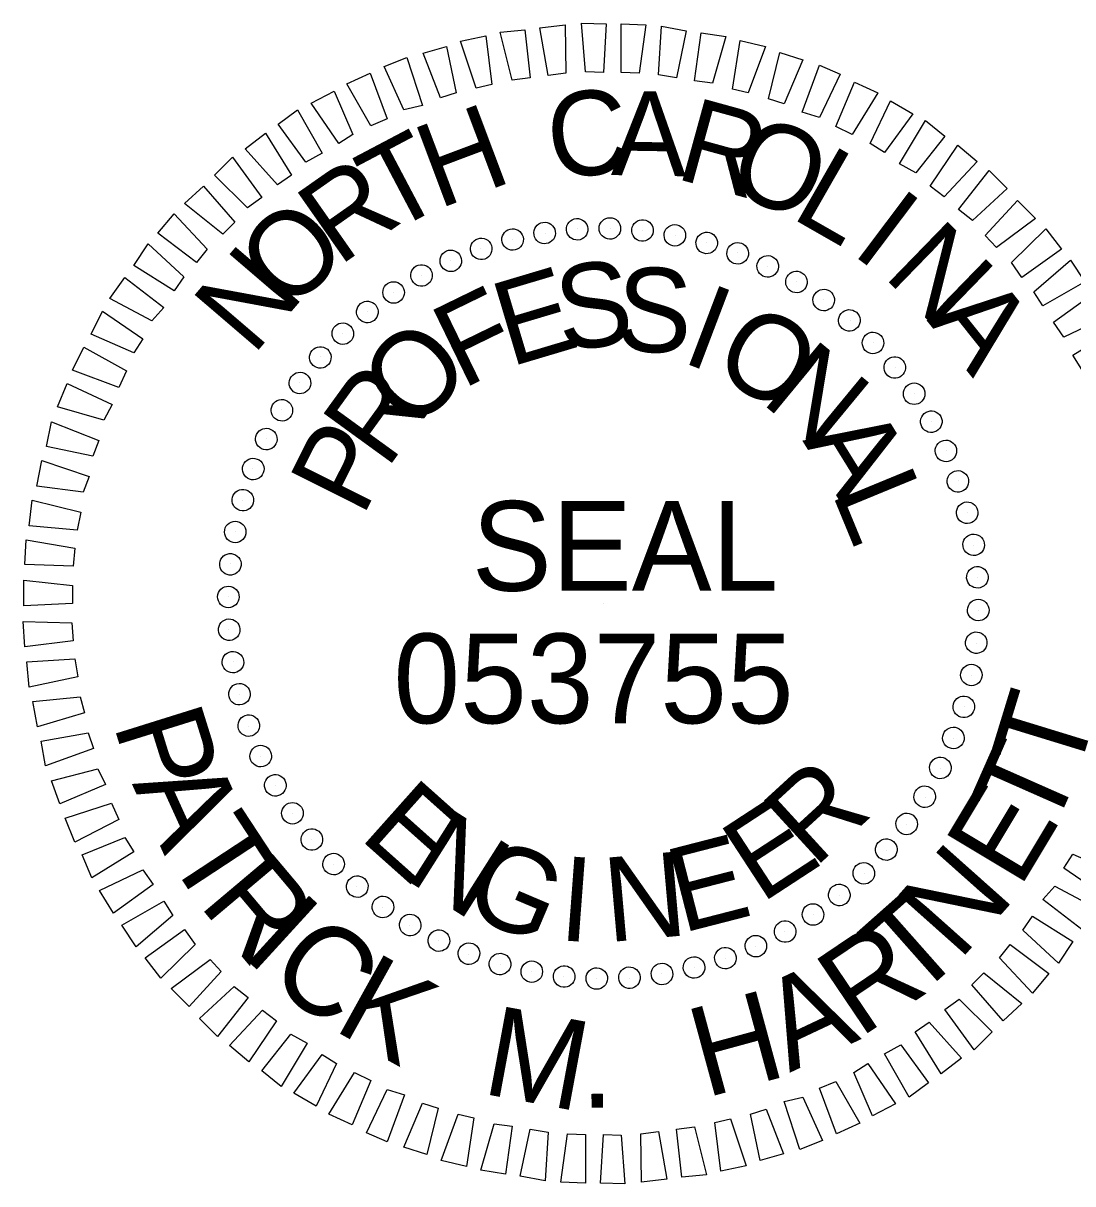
# Model space of a CAD drawing. Extents: x 1184048.9 to 1184122, y 1246638.9 to 1246660.6.
# Drawn here: x 1184117.624 to 1184120.43, y 1246652.546 to 1246655.648 of the extents above; entities that cross this region are included whole.
import ezdxf

# ---------------------------------------------------------------- set-up
doc = ezdxf.new("R2010")
doc.units = 0
doc.layers.add('Sheet PE Seal CELL', color=7, linetype='Continuous')

msp = doc.modelspace()

# ---------------------------------------------------------------- linework, layer by layer
at = {"layer": 'Sheet PE Seal CELL'}
for p, q in [((1184119.1053, 1246655.098), (1184119.1053, 1246655.098)), ((1184119.1932, 1246655.1), (1184119.1932, 1246655.1)), ((1184118.9314, 1246655.07), (1184118.9314, 1246655.07)), ((1184119.0194, 1246655.086), (1184119.0194, 1246655.086)), ((1184119.2812, 1246655.094), (1184119.2812, 1246655.094)), ((1184119.3671, 1246655.08), (1184119.3671, 1246655.08)), ((1184118.8475, 1246655.046), (1184118.8475, 1246655.046)), ((1184119.451, 1246655.062), (1184119.451, 1246655.062)), ((1184118.7676, 1246655.014), (1184118.7676, 1246655.014)), ((1184119.535, 1246655.034), (1184119.535, 1246655.034)), ((1184118.6896, 1246654.9741), (1184118.6896, 1246654.9741)), ((1184119.6149, 1246654.998), (1184119.6149, 1246654.998)), ((1184119.6928, 1246654.9581), (1184119.6928, 1246654.9581)), ((1184118.6137, 1246654.9281), (1184118.6137, 1246654.9281)), ((1184119.7648, 1246654.9081), (1184119.7648, 1246654.9081)), ((1184118.5438, 1246654.8781), (1184118.5438, 1246654.8781)), ((1184119.8347, 1246654.8542), (1184119.8347, 1246654.8542)), ((1184118.4778, 1246654.8182), (1184118.4778, 1246654.8182)), ((1184119.8967, 1246654.7942), (1184119.8967, 1246654.7942)), ((1184118.4179, 1246654.7562), (1184118.4179, 1246654.7562)), ((1184119.9566, 1246654.7283), (1184119.9566, 1246654.7283)), ((1184118.3639, 1246654.6863), (1184118.3639, 1246654.6863)), ((1184120.0066, 1246654.6583), (1184120.0066, 1246654.6583)), ((1184118.3139, 1246654.6143), (1184118.3139, 1246654.6143)), ((1184120.0526, 1246654.5824), (1184120.0526, 1246654.5824)), ((1184118.274, 1246654.5364), (1184118.274, 1246654.5364)), ((1184120.0925, 1246654.5044), (1184120.0925, 1246654.5044)), ((1184118.238, 1246654.4565), (1184118.238, 1246654.4565)), ((1184120.1245, 1246654.4245), (1184120.1245, 1246654.4245)), ((1184118.21, 1246654.3725), (1184118.21, 1246654.3725)), ((1184120.1485, 1246654.3406), (1184120.1485, 1246654.3406)), ((1184118.192, 1246654.2886), (1184118.192, 1246654.2886)), ((1184120.1645, 1246654.2526), (1184120.1645, 1246654.2526)), ((1184118.1781, 1246654.2027), (1184118.1781, 1246654.2027)), ((1184120.1765, 1246654.1667), (1184120.1765, 1246654.1667)), ((1184118.1721, 1246654.1147), (1184118.1721, 1246654.1147)), ((1184119.1753, 1246654.0968), (1184119.1753, 1246654.0968)), ((1184120.1785, 1246654.0788), (1184120.1785, 1246654.0788)), ((1184118.1741, 1246654.0268), (1184118.1741, 1246654.0268)), ((1184120.1725, 1246653.9908), (1184120.1725, 1246653.9908)), ((1184118.186, 1246653.9409), (1184118.186, 1246653.9409)), ((1184120.1585, 1246653.9049), (1184120.1585, 1246653.9049)), ((1184118.202, 1246653.853), (1184118.202, 1246653.853)), ((1184120.1405, 1246653.821), (1184120.1405, 1246653.821)), ((1184118.226, 1246653.769), (1184118.226, 1246653.769)), ((1184120.1125, 1246653.737), (1184120.1125, 1246653.737)), ((1184118.258, 1246653.6891), (1184118.258, 1246653.6891)), ((1184120.0765, 1246653.6571), (1184120.0765, 1246653.6571)), ((1184118.298, 1246653.6112), (1184118.298, 1246653.6112)), ((1184120.0366, 1246653.5792), (1184120.0366, 1246653.5792)), ((1184118.3439, 1246653.5352), (1184118.3439, 1246653.5352)), ((1184119.9866, 1246653.5072), (1184119.9866, 1246653.5072)), ((1184118.3939, 1246653.4653), (1184118.3939, 1246653.4653)), ((1184119.9327, 1246653.4373), (1184119.9327, 1246653.4373)), ((1184118.4538, 1246653.3993), (1184118.4538, 1246653.3993)), ((1184119.8727, 1246653.3753), (1184119.8727, 1246653.3753)), ((1184118.5158, 1246653.3394), (1184118.5158, 1246653.3394)), ((1184119.8068, 1246653.3154), (1184119.8068, 1246653.3154)), ((1184118.5857, 1246653.2854), (1184118.5857, 1246653.2854)), ((1184119.7368, 1246653.2654), (1184119.7368, 1246653.2654)), ((1184118.6577, 1246653.2355), (1184118.6577, 1246653.2355)), ((1184119.6609, 1246653.2195), (1184119.6609, 1246653.2195)), ((1184118.7356, 1246653.1955), (1184118.7356, 1246653.1955)), ((1184119.5829, 1246653.1795), (1184119.5829, 1246653.1795)), ((1184118.8155, 1246653.1595), (1184118.8155, 1246653.1595)), ((1184119.503, 1246653.1475), (1184119.503, 1246653.1475)), ((1184118.8995, 1246653.1315), (1184118.8995, 1246653.1315)), ((1184118.9834, 1246653.1135), (1184118.9834, 1246653.1135)), ((1184119.4191, 1246653.1235), (1184119.4191, 1246653.1235)), ((1184119.0693, 1246653.0996), (1184119.0693, 1246653.0996)), ((1184119.1573, 1246653.0936), (1184119.1573, 1246653.0936)), ((1184119.2452, 1246653.0956), (1184119.2452, 1246653.0956)), ((1184119.3311, 1246653.1076), (1184119.3311, 1246653.1076))]:
    msp.add_line(p, q, dxfattribs=at)
for points in [[(1184118.9314, 1246655.4956), (1184118.8995, 1246655.6235), (1184118.9654, 1246655.6295), (1184118.9794, 1246655.5016)], [(1184119.0274, 1246655.5076), (1184119.0054, 1246655.6355), (1184119.0733, 1246655.6435), (1184119.0753, 1246655.5136)], [(1184119.1273, 1246655.5176), (1184119.1173, 1246655.6475), (1184119.1832, 1246655.6455), (1184119.1753, 1246655.5156)], [(1184119.2232, 1246655.5156), (1184119.2232, 1246655.6455), (1184119.2892, 1246655.6435), (1184119.2712, 1246655.5136)], [(1184119.3231, 1246655.5096), (1184119.3311, 1246655.6395), (1184119.3971, 1246655.6275), (1184119.3711, 1246655.5016)], [(1184118.8355, 1246655.4737), (1184118.7936, 1246655.5996), (1184118.8615, 1246655.6136), (1184118.8775, 1246655.4837)], [(1184119.4191, 1246655.4936), (1184119.437, 1246655.6215), (1184119.503, 1246655.6116), (1184119.467, 1246655.4877)], [(1184119.521, 1246655.4717), (1184119.541, 1246655.6016), (1184119.6089, 1246655.5856), (1184119.5629, 1246655.4617)], [(1184118.7396, 1246655.4477), (1184118.6936, 1246655.5676), (1184118.7556, 1246655.5856), (1184118.7816, 1246655.4617)], [(1184119.6169, 1246655.4457), (1184119.6469, 1246655.5696), (1184119.7088, 1246655.5496), (1184119.6589, 1246655.4317)], [(1184118.6417, 1246655.4157), (1184118.5897, 1246655.5316), (1184118.6497, 1246655.5556), (1184118.6916, 1246655.4277)], [(1184119.7068, 1246655.4097), (1184119.7528, 1246655.5356), (1184119.8087, 1246655.5116), (1184119.7528, 1246655.3957)], [(1184118.5538, 1246655.3737), (1184118.4898, 1246655.4857), (1184118.5518, 1246655.5136), (1184118.5977, 1246655.3917)], [(1184119.7968, 1246655.3717), (1184119.8467, 1246655.4897), (1184119.9087, 1246655.4617), (1184119.8407, 1246655.3498)], [(1184118.4678, 1246655.3258), (1184118.3939, 1246655.4337), (1184118.4558, 1246655.4657), (1184118.5058, 1246655.3498)], [(1184119.8887, 1246655.3258), (1184119.9426, 1246655.4397), (1184120.0026, 1246655.4057), (1184119.9267, 1246655.3018)], [(1184118.3799, 1246655.2758), (1184118.3059, 1246655.3777), (1184118.3579, 1246655.4157), (1184118.4239, 1246655.2998)], [(1184119.9666, 1246655.2718), (1184120.0366, 1246655.3877), (1184120.0885, 1246655.3458), (1184120.0106, 1246655.2478)], [(1184118.304, 1246655.2159), (1184118.218, 1246655.3118), (1184118.272, 1246655.3538), (1184118.3419, 1246655.2418)], [(1184120.0486, 1246655.2119), (1184120.1225, 1246655.3218), (1184120.1745, 1246655.2778), (1184120.0865, 1246655.1839)], [(1184118.224, 1246655.1539), (1184118.1361, 1246655.2418), (1184118.184, 1246655.2898), (1184118.262, 1246655.1819)], [(1184120.1245, 1246655.1499), (1184120.2064, 1246655.2538), (1184120.2544, 1246655.2059), (1184120.1625, 1246655.1199)], [(1184118.1581, 1246655.084), (1184118.0561, 1246655.1659), (1184118.1061, 1246655.2119), (1184118.19, 1246655.1159)], [(1184120.1964, 1246655.08), (1184120.2824, 1246655.1739), (1184120.3303, 1246655.1259), (1184120.2264, 1246655.048)], [(1184118.0881, 1246655.008), (1184117.9842, 1246655.086), (1184118.0282, 1246655.1379), (1184118.1161, 1246655.044)], [(1184120.2664, 1246655.008), (1184120.3583, 1246655.098), (1184120.4003, 1246655.044), (1184120.2944, 1246654.9681)], [(1184118.0282, 1246654.9321), (1184117.9203, 1246655), (1184117.9582, 1246655.058), (1184118.0542, 1246654.9701)], [(1184120.3263, 1246654.9301), (1184120.4243, 1246655.014), (1184120.4622, 1246654.9561), (1184120.3503, 1246654.8921)], [(1184117.9682, 1246654.8522), (1184117.8563, 1246654.9121), (1184117.8963, 1246654.9681), (1184118.0002, 1246654.8881)], [(1184120.3783, 1246654.8482), (1184120.4842, 1246654.9241), (1184120.5222, 1246654.8641), (1184120.4063, 1246654.8082)], [(1184117.9203, 1246654.7662), (1184117.8063, 1246654.8162), (1184117.8363, 1246654.8781), (1184117.9442, 1246654.8042)], [(1184120.4303, 1246654.7602), (1184120.5422, 1246654.8302), (1184120.5681, 1246654.7682), (1184120.4542, 1246654.7223)], [(1184117.8803, 1246654.6743), (1184117.7564, 1246654.7203), (1184117.7864, 1246654.7822), (1184117.9003, 1246654.7183)], [(1184117.8403, 1246654.5864), (1184117.7164, 1246654.6223), (1184117.7424, 1246654.6843), (1184117.8623, 1246654.6283)], [(1184117.8103, 1246654.4904), (1184117.6864, 1246654.5164), (1184117.7004, 1246654.5824), (1184117.8263, 1246654.5324)], [(1184117.7844, 1246654.3945), (1184117.6605, 1246654.4105), (1184117.6745, 1246654.4785), (1184117.8004, 1246654.4365)], [(1184117.7684, 1246654.2926), (1184117.6405, 1246654.3046), (1184117.6485, 1246654.3725), (1184117.7784, 1246654.3406)], [(1184117.7584, 1246654.1967), (1184117.6285, 1246654.2007), (1184117.6325, 1246654.2666), (1184117.7624, 1246654.2446)], [(1184117.7564, 1246654.0968), (1184117.6265, 1246654.0908), (1184117.6265, 1246654.1587), (1184117.7564, 1246654.1447)], [(1184117.7584, 1246653.9968), (1184117.6285, 1246653.9809), (1184117.6245, 1246654.0488), (1184117.7544, 1246654.0448)], [(1184117.7704, 1246653.9009), (1184117.6405, 1246653.8729), (1184117.6345, 1246653.9409), (1184117.7624, 1246653.9489)], [(1184117.7884, 1246653.805), (1184117.6625, 1246653.767), (1184117.6505, 1246653.835), (1184117.7764, 1246653.847)], [(1184117.8123, 1246653.7091), (1184117.6844, 1246653.6631), (1184117.6725, 1246653.7291), (1184117.7984, 1246653.751)], [(1184117.8443, 1246653.6131), (1184117.7224, 1246653.5612), (1184117.7004, 1246653.6231), (1184117.8243, 1246653.6551)], [(1184117.8803, 1246653.5192), (1184117.7624, 1246653.4593), (1184117.7364, 1246653.5232), (1184117.8603, 1246653.5632)], [(1184117.9203, 1246653.4333), (1184117.8083, 1246653.3633), (1184117.7824, 1246653.4253), (1184117.8963, 1246653.4713)], [(1184120.4303, 1246653.4273), (1184120.5442, 1246653.3773), (1184120.5142, 1246653.3154), (1184120.4063, 1246653.3893)], [(1184117.9722, 1246653.3454), (1184117.8663, 1246653.2694), (1184117.8283, 1246653.3294), (1184117.9442, 1246653.3853)], [(1184120.3823, 1246653.3414), (1184120.4942, 1246653.2814), (1184120.4542, 1246653.2255), (1184120.3503, 1246653.3054)], [(1184118.0242, 1246653.2634), (1184117.9263, 1246653.1795), (1184117.8883, 1246653.2374), (1184118.0002, 1246653.3014)], [(1184120.3223, 1246653.2614), (1184120.4303, 1246653.1935), (1184120.3923, 1246653.1355), (1184120.2964, 1246653.2235)], [(1184118.0841, 1246653.1855), (1184117.9922, 1246653.0956), (1184117.9502, 1246653.1495), (1184118.0561, 1246653.2255)], [(1184120.2624, 1246653.1855), (1184120.3663, 1246653.1076), (1184120.3223, 1246653.0556), (1184120.2344, 1246653.1495)], [(1184118.1541, 1246653.1135), (1184118.0681, 1246653.0196), (1184118.0202, 1246653.0676), (1184118.1241, 1246653.1455)], [(1184120.1924, 1246653.1096), (1184120.2944, 1246653.0276), (1184120.2444, 1246652.9817), (1184120.1605, 1246653.0776)], [(1184118.226, 1246653.0436), (1184118.1441, 1246652.9397), (1184118.0961, 1246652.9876), (1184118.188, 1246653.0736)], [(1184120.1265, 1246653.0396), (1184120.2144, 1246652.9517), (1184120.1665, 1246652.9037), (1184120.0885, 1246653.0116)], [(1184118.302, 1246652.9817), (1184118.228, 1246652.8717), (1184118.1761, 1246652.9157), (1184118.264, 1246653.0096)], [(1184120.0466, 1246652.9777), (1184120.1325, 1246652.8817), (1184120.0785, 1246652.8398), (1184120.0086, 1246652.9517)], [(1184118.3839, 1246652.9217), (1184118.3139, 1246652.8058), (1184118.262, 1246652.8478), (1184118.3399, 1246652.9457)], [(1184119.9706, 1246652.9177), (1184120.0446, 1246652.8158), (1184119.9926, 1246652.7778), (1184119.9267, 1246652.8937)], [(1184118.4618, 1246652.8677), (1184118.4079, 1246652.7538), (1184118.3479, 1246652.7878), (1184118.4239, 1246652.8917)], [(1184119.8827, 1246652.8677), (1184119.9566, 1246652.7598), (1184119.8947, 1246652.7279), (1184119.8447, 1246652.8438)], [(1184118.5538, 1246652.8218), (1184118.5038, 1246652.7039), (1184118.4418, 1246652.7319), (1184118.5098, 1246652.8438)], [(1184119.7968, 1246652.8198), (1184119.8607, 1246652.7079), (1184119.7988, 1246652.6799), (1184119.7528, 1246652.8018)], [(1184118.6437, 1246652.7838), (1184118.5977, 1246652.6579), (1184118.5418, 1246652.6819), (1184118.5977, 1246652.7978)], [(1184119.7088, 1246652.7778), (1184119.7608, 1246652.6619), (1184119.7008, 1246652.6379), (1184119.6589, 1246652.7658)], [(1184118.7336, 1246652.7478), (1184118.7036, 1246652.6239), (1184118.6417, 1246652.6439), (1184118.6916, 1246652.7618)], [(1184119.6109, 1246652.7458), (1184119.6569, 1246652.6259), (1184119.5949, 1246652.608), (1184119.5689, 1246652.7319)], [(1184118.8295, 1246652.7219), (1184118.8095, 1246652.592), (1184118.7416, 1246652.608), (1184118.7876, 1246652.7319)], [(1184119.515, 1246652.7199), (1184119.557, 1246652.594), (1184119.489, 1246652.58), (1184119.473, 1246652.7099)], [(1184118.9314, 1246652.6999), (1184118.9135, 1246652.572), (1184118.8475, 1246652.582), (1184118.8835, 1246652.7059)], [(1184119.0274, 1246652.6839), (1184119.0194, 1246652.554), (1184118.9534, 1246652.566), (1184118.9794, 1246652.6919)], [(1184119.1273, 1246652.6779), (1184119.1273, 1246652.548), (1184119.0613, 1246652.55), (1184119.0793, 1246652.6799)], [(1184119.3231, 1246652.6859), (1184119.3451, 1246652.558), (1184119.2772, 1246652.55), (1184119.2752, 1246652.6799)], [(1184119.4191, 1246652.6979), (1184119.451, 1246652.57), (1184119.3851, 1246652.564), (1184119.3711, 1246652.6919)], [(1184119.2232, 1246652.6759), (1184119.2332, 1246652.546), (1184119.1673, 1246652.548), (1184119.1753, 1246652.6779)]]:
    msp.add_lwpolyline(points, close=True, dxfattribs=at)
for centre, major_axis in [((1184118.9328, 1246655.0694), (-0.007, 0.0279)), ((1184119.0184, 1246655.0868), (-0.0045, 0.0284)), ((1184119.1053, 1246655.0967), (-0.002, 0.0287)), ((1184119.1927, 1246655.099), (0.0005, 0.0288)), ((1184119.28, 1246655.0937), (0.003, 0.0286)), ((1184119.3665, 1246655.0807), (0.0055, 0.0282)), ((1184118.8489, 1246655.0445), (-0.0094, 0.0272)), ((1184119.4516, 1246655.0603), (0.0079, 0.0277)), ((1184118.7675, 1246655.0125), (-0.0117, 0.0263)), ((1184119.5345, 1246655.0326), (0.0103, 0.0269)), ((1184118.6893, 1246654.9735), (-0.014, 0.0252)), ((1184119.6147, 1246654.9977), (0.0126, 0.0259)), ((1184119.6915, 1246654.956), (0.0148, 0.0247)), ((1184118.6147, 1246654.9278), (-0.0161, 0.0239)), ((1184119.7645, 1246654.9077), (0.0169, 0.0233)), ((1184118.5444, 1246654.8758), (-0.0181, 0.0224)), ((1184119.8329, 1246654.8533), (0.0189, 0.0217)), ((1184118.4789, 1246654.8178), (-0.02, 0.0207)), ((1184119.8963, 1246654.7931), (0.0207, 0.02)), ((1184118.4187, 1246654.7544), (-0.0217, 0.0189)), ((1184119.9543, 1246654.7276), (0.0224, 0.0181)), ((1184118.3643, 1246654.686), (-0.0233, 0.0169)), ((1184120.0063, 1246654.6573), (0.0239, 0.0161)), ((1184118.316, 1246654.613), (-0.0247, 0.0148)), ((1184120.052, 1246654.5827), (0.0252, 0.014)), ((1184118.2743, 1246654.5362), (-0.0259, 0.0126)), ((1184120.091, 1246654.5045), (0.0263, 0.0117)), ((1184118.2394, 1246654.456), (-0.0269, 0.0103)), ((1184120.123, 1246654.4231), (0.0272, 0.0094)), ((1184118.2117, 1246654.3731), (-0.0277, 0.0079)), ((1184120.1479, 1246654.3393), (0.0279, 0.007)), ((1184118.1913, 1246654.288), (-0.0282, 0.0055)), ((1184120.1653, 1246654.2536), (0.0284, 0.0045)), ((1184118.1783, 1246654.2015), (-0.0286, 0.003)), ((1184120.1752, 1246654.1667), (0.0287, 0.002)), ((1184118.173, 1246654.1143), (-0.0288, 0.0005)), ((1184120.1775, 1246654.0793), (0.0288, -0.0005)), ((1184118.1753, 1246654.0268), (-0.0287, -0.002)), ((1184120.1722, 1246653.992), (0.0286, -0.003)), ((1184118.1852, 1246653.94), (-0.0284, -0.0045)), ((1184120.1592, 1246653.9055), (0.0282, -0.0055)), ((1184118.2026, 1246653.8543), (-0.0279, -0.007)), ((1184120.1388, 1246653.8205), (0.0277, -0.0079)), ((1184118.2275, 1246653.7704), (-0.0272, -0.0094)), ((1184120.1111, 1246653.7375), (0.0269, -0.0103)), ((1184118.2595, 1246653.689), (-0.0263, -0.0117)), ((1184120.0762, 1246653.6573), (0.0259, -0.0126)), ((1184118.2985, 1246653.6108), (-0.0252, -0.014)), ((1184120.0345, 1246653.5805), (0.0247, -0.0148)), ((1184118.3442, 1246653.5362), (-0.0239, -0.0161)), ((1184119.9862, 1246653.5076), (0.0233, -0.0169)), ((1184118.3962, 1246653.4659), (-0.0224, -0.0181)), ((1184119.9318, 1246653.4391), (0.0217, -0.0189)), ((1184118.4542, 1246653.4004), (-0.0207, -0.02)), ((1184119.8716, 1246653.3757), (0.02, -0.0207)), ((1184118.5176, 1246653.3402), (-0.0189, -0.0217)), ((1184119.8061, 1246653.3178), (0.0181, -0.0224)), ((1184118.5861, 1246653.2858), (-0.0169, -0.0233)), ((1184118.659, 1246653.2375), (-0.0148, -0.0247)), ((1184119.7358, 1246653.2657), (0.0161, -0.0239)), ((1184119.6612, 1246653.22), (0.014, -0.0252)), ((1184118.7358, 1246653.1958), (-0.0126, -0.0259)), ((1184119.583, 1246653.181), (0.0117, -0.0263)), ((1184118.816, 1246653.1609), (-0.0103, -0.0269)), ((1184119.5016, 1246653.149), (0.0094, -0.0272)), ((1184118.899, 1246653.1332), (-0.0079, -0.0277)), ((1184118.984, 1246653.1128), (-0.0055, -0.0282)), ((1184119.4178, 1246653.1241), (0.007, -0.0279)), ((1184119.0705, 1246653.0999), (-0.003, -0.0286)), ((1184119.1578, 1246653.0945), (-0.0005, -0.0288)), ((1184119.2452, 1246653.0968), (0.002, -0.0287)), ((1184119.3321, 1246653.1067), (0.0045, -0.0284))]:
    msp.add_ellipse(centre, major_axis=major_axis, ratio=0.999708, dxfattribs=at)

# ---------------------------------------------------------------- texts
for s, height, rotation, p in [('C', 0.2253, 6.2199, (1184119.0374, 1246655.2299)), ('A', 0.2253, 359.0203, (1184119.1952, 1246655.2418)), ('R', 0.2253, 344.6211, (1184119.3631, 1246655.2339)), ('H', 0.2253, 20.6195, (1184118.7336, 1246655.1499)), ('O', 0.2253, 337.4212, (1184119.497, 1246655.2039)), ('T', 0.2253, 27.8198, (1184118.6037, 1246655.084)), ('L', 0.2253, 330.2209, (1184119.6729, 1246655.1299)), ('R', 0.2254, 35.0205, (1184118.4678, 1246654.996)), ('I', 0.2253, 323.0201, (1184119.8347, 1246655.034)), ('O', 0.2254, 42.2217, (1184118.3299, 1246654.8721)), ('N', 0.2254, 315.8189, (1184119.9207, 1246654.9721)), ('N', 0.2254, 49.4235, (1184118.238, 1246654.7562)), ('S', 0.2253, 7.2556, (1184119.0633, 1246654.7702)), ('E', 0.2253, 16.6111, (1184118.9255, 1246654.7283)), ('S', 0.2253, 357.9004, (1184119.2072, 1246654.7722)), ('F', 0.2253, 25.967, (1184118.7976, 1246654.6683)), ('I', 0.2253, 339.1896, (1184119.3791, 1246654.7442)), ('A', 0.2254, 308.6172, (1184120.0386, 1246654.8542)), ('O', 0.2253, 329.8335, (1184119.459, 1246654.7163)), ('O', 0.2254, 44.6812, (1184118.6657, 1246654.5504)), ('N', 0.2254, 320.4766, (1184119.5929, 1246654.6363)), ('R', 0.2254, 54.0397, (1184118.5957, 1246654.4525)), ('P', 0.2254, 63.3989, (1184118.5318, 1246654.3246)), ('A', 0.2254, 301.7603, (1184119.7068, 1246654.5324)), ('L', 0.2254, 292.4008, (1184119.7848, 1246654.3945)), ('SEAL', 0.23974, 360, (1184118.8236, 1246654.1307)), ('T', 0.2397, 72.9557, (1184120.4385, 1246653.6221)), ('P', 0.2397, 287.3534, (1184117.8647, 1246653.7748)), ('T', 0.2397, 66.1555, (1184120.3735, 1246653.4758)), ('R', 0.2254, 42.4814, (1184119.7388, 1246653.3873)), ('A', 0.2397, 294.4627, (1184117.9146, 1246653.6151)), ('E', 0.2253, 318.2769, (1184118.5198, 1246653.4713)), ('E', 0.2397, 59.0461, (1184120.2874, 1246653.3323)), ('E', 0.2254, 33.1241, (1184119.5969, 1246653.2934)), ('T', 0.2397, 303.303, (1184118.0036, 1246653.427)), ('N', 0.2254, 327.634, (1184118.6397, 1246653.3633)), ('G', 0.2253, 336.9902, (1184118.7916, 1246653.2734)), ('E', 0.2253, 14.4118, (1184119.3851, 1246653.2155)), ('R', 0.2397, 310.1033, (1184118.0912, 1246653.293)), ('N', 0.2253, 5.0564, (1184119.1872, 1246653.1915)), ('N', 0.2397, 48.3203, (1184120.1257, 1246653.1387)), ('I', 0.2253, 355.7012, (1184119.0534, 1246653.1975)), ('T', 0.2397, 41.5201, (1184120.0056, 1246653.0329)), ('I', 0.2397, 317.5835, (1184118.205, 1246653.1587)), ('C', 0.2397, 321.3855, (1184118.2694, 1246653.0965)), ('R', 0.2397, 34.0398, (1184119.86, 1246652.9338)), ('K', 0.2397, 330.9676, (1184118.4485, 1246652.9596)), ('A', 0.2397, 25.1995, (1184119.6731, 1246652.8424)), ('H', 0.2397, 15.2155, (1184119.4481, 1246652.7751)), ('M', 0.2397, 349.4519, (1184118.8465, 1246652.7879)), ('.', 0.2397, 0.9814, (1184119.1148, 1246652.7486))]:
    msp.add_text(s, height=height, rotation=rotation, dxfattribs=at).set_placement(p)
msp.add_text('053755', height=0.23974, dxfattribs=at).set_placement((1184118.6142, 1246653.7767))

doc.saveas('drawing.dxf')
